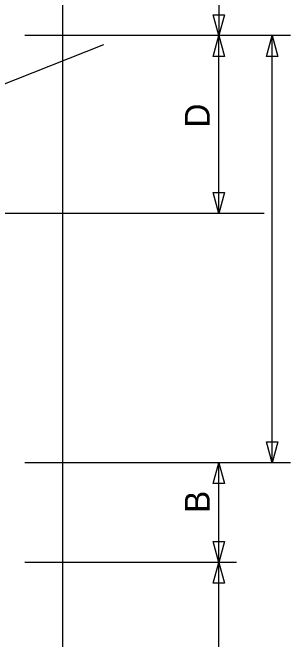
# Model space of a CAD drawing. Extents: x 16038 to 19504, y 5710 to 8321.
# Drawn here: x 17124.7 to 17202.8, y 6320.5 to 6496.9 of the extents above; entities that cross this region are included whole.
import ezdxf

# ---------------------------------------------------------------- set-up
doc = ezdxf.new("R2010")
doc.units = 0
doc.layers.add('PAVT_EDGE_EX', color=7, linetype='Continuous')
doc.layers.add('TYPICAL_TEXT_DIMEN_PR', color=7, linetype='Continuous')

msp = doc.modelspace()

# ---------------------------------------------------------------- linework, layer by layer
at = {"layer": 'PAVT_EDGE_EX'}
msp.add_line((17138.71, 6925.32), (17138.71, 6077.44), dxfattribs=at)
at = {"layer": 'TYPICAL_TEXT_DIMEN_PR'}
for p, q in [((17182.71, 6514.82), (17182.71, 6490.36)), ((17182.71, 6490.36), (17181.14, 6496.22)), ((17181.14, 6496.22), (17182.71, 6496.22)), ((17182.71, 6496.22), (17184.28, 6496.22)), ((17184.28, 6496.22), (17182.71, 6490.36)), ((17202.83, 6490.36), (17128.21, 6490.36)), ((17181.14, 6484.5), (17182.71, 6490.36)), ((17182.71, 6440.36), (17182.71, 6490.36)), ((17182.71, 6490.36), (17184.28, 6484.5)), ((17196.14, 6484.5), (17197.71, 6490.36)), ((17197.71, 6370.19), (17197.71, 6490.36)), ((17197.71, 6490.36), (17199.28, 6484.5)), ((17150.26, 6487.79), (17042.17, 6445.05)), ((17182.71, 6484.5), (17181.14, 6484.5)), ((17184.28, 6484.5), (17182.71, 6484.5)), ((17197.71, 6484.5), (17196.14, 6484.5)), ((17199.28, 6484.5), (17197.71, 6484.5)), ((17182.71, 6440.36), (17181.14, 6446.22)), ((17181.14, 6446.22), (17182.71, 6446.22)), ((17182.71, 6446.22), (17184.28, 6446.22)), ((17184.28, 6446.22), (17182.71, 6440.36)), ((17195.41, 6440.36), (17057.15, 6440.36)), ((17197.71, 6370.19), (17196.14, 6376.05)), ((17196.14, 6376.05), (17197.71, 6376.05)), ((17197.71, 6376.05), (17199.28, 6376.05)), ((17199.28, 6376.05), (17197.71, 6370.19)), ((17202.83, 6370.19), (17128.21, 6370.19)), ((17181.14, 6364.32), (17182.71, 6370.19)), ((17182.71, 6342.13), (17182.71, 6370.19)), ((17182.71, 6370.19), (17184.28, 6364.32)), ((17182.71, 6364.32), (17181.14, 6364.32)), ((17184.28, 6364.32), (17182.71, 6364.32)), ((17182.71, 6342.13), (17181.14, 6347.99)), ((17181.14, 6347.99), (17182.71, 6347.99)), ((17182.71, 6347.99), (17184.28, 6347.99)), ((17184.28, 6347.99), (17182.71, 6342.13)), ((17187.71, 6342.13), (17128.21, 6342.13)), ((17181.14, 6336.27), (17182.71, 6342.13)), ((17182.71, 6342.13), (17184.28, 6336.27)), ((17182.71, 6280.46), (17182.71, 6342.13)), ((17182.71, 6336.27), (17181.14, 6336.27)), ((17184.28, 6336.27), (17182.71, 6336.27))]:
    msp.add_line(p, q, dxfattribs=at)

# ---------------------------------------------------------------- texts
for s, p in [('D', (17180.15, 6464.48)), ('B', (17180.15, 6356.07))]:
    msp.add_text(s, height=7, rotation=90, dxfattribs=at).set_placement(p)

doc.saveas('drawing.dxf')
